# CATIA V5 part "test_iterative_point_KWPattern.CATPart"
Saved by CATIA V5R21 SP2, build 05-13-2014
Part number: Part1
Bounding box of the stored display mesh (mm): x 0 to 79.792, y -93.782 to 0, z 0 to 0
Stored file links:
  \\sfs.corp\Projects\OTHERS\CHANNEL_KEY_USER\01_3DCOM-VPM\Deliverables\Pos25_CV4_Functions\Create_Curtain\tmp\test_iterative_point_KWPattern.CATPart
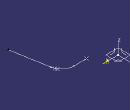
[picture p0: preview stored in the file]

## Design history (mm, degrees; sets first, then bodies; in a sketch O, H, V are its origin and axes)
Parameters
  Spacing_Vorgabe = 40 mm
  Distance_Points_First_Iteration = 37.9596 mm
  Distance_Points_Last_Iteration = 40.0427 mm
  Number_of_Iterations = 3
  Iteration_Value = 1.5 mm
AxisSystem1: origin (0, 0, 0), X (1, 0, 0), Y (0, 1, 0), Z (0, 0, 1)
Set1
  Plane1: type Offset, RefPlane XY plane of AxisSystem1, Offset 0
  Project1: ToProject Sketch1, Support Plane1
  Point1: type OnCurve, Support Project1, Length 0
  Point2 "Point_Spacing.1": stored without definition
  Point3 "Point_Spacing_ITERAT.2": stored without definition
  Point4 "Point_Spacing_Final": stored without definition
Body1 (main body)
  Sketch1 on Plane1, origin (0, 0, 0), H (1, 0, 0), V (0, 1, 0)
    point P1 (30, -20)
    line L1 (30, -20) -> (50, -20)
    point P2 (50, -20)
    arc A1 centre (50, -40) radius 20 from (50, -20) to (69.6962, -36.527) cw
    line L2 (69.6962, -36.527) -> (79.7917, -93.7816)
    radius A1 = 20
    distance P1 P2 = 20
    distance L1 H = 20
    distance V A1 = 30
    length L2 = 58.1378
    angle L2 L1 = 100
    horizontal: L1 H
    tangency: A1 L1, L2 A1
    perpendicularity: L1 V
